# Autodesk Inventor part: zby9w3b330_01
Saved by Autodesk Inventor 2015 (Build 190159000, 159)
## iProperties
Created: 2019-08
Part Number: zby9w3b330_01
Checked By: TraceParts S.A.
Material: Générique
Catalog Web Link: www.traceparts.com
Document SubType Name: Modeling
Designer: TraceParts
Density: 1 g/cm^3
Appearance: Par défaut
Company: TraceParts S.A.
Author: TraceParts
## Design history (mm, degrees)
feature "zby9w3b330_01.ipt"
node "Solide1"
